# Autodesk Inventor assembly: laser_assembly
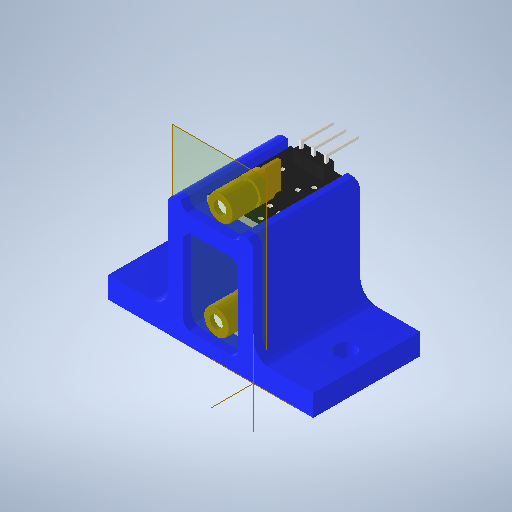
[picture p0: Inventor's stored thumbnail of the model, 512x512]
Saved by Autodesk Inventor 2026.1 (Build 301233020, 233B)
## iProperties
Created: 2026-10
Part Number: laser_assembly
Document SubType Name: Assembly
Designer: alolo
Author: alolo
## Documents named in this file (3)
- C:\Users\hp\Documents\Inventor\DOM1_CartesianRobot\laser_assembly.iam
- C:\Users\hp\Documents\Inventor\DOM1_CartesianRobot\laser_rack.ipt
- C:\Users\hp\Documents\Inventor\DOM1_CartesianRobot\650nm Laser Transmitter Module (KY-008).ipt
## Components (3 placed, 2 different names)
1. laser_rack:1 — Mate:1, Mate:2, Mate:3, Mate:4, Mate:5, Mate:6, Mate:7, Angle:1
2. 650nm Laser Transmitter Module (KY-008):1 — Mate:3, Mate:4, Mate:9
3. 650nm Laser Transmitter Module (KY-008):2 — Mate:5, Mate:6, Mate:8
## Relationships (10: Mate 9, Angle 1)
- Mate:1: laser_rack:1
- Mate:2: laser_rack:1
- Mate:3: laser_rack:1 ↔ 650nm Laser Transmitter Module (KY-008):1
- Mate:4: laser_rack:1 ↔ 650nm Laser Transmitter Module (KY-008):1
- Mate:5: laser_rack:1 ↔ 650nm Laser Transmitter Module (KY-008):2
- Mate:6: laser_rack:1 ↔ 650nm Laser Transmitter Module (KY-008):2
- Mate:7: laser_rack:1
- Angle:1: laser_rack:1
- Mate:8: 650nm Laser Transmitter Module (KY-008):2
- Mate:9: 650nm Laser Transmitter Module (KY-008):1
